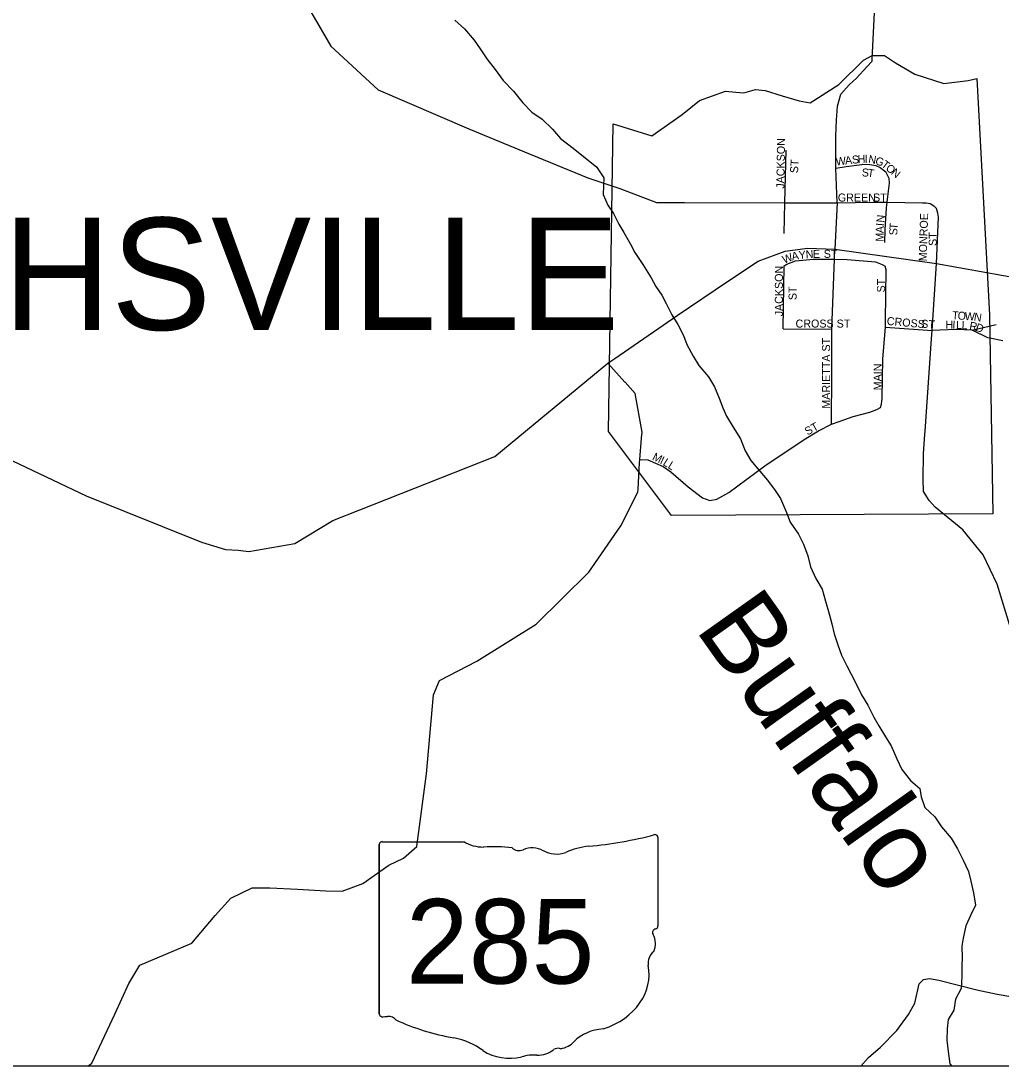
# Model space of a CAD drawing. Extents: x -22 to 431, y -18 to 160.
# Drawn here: x -3.877 to -2.717, y 14.134 to 15.371 of the extents above; entities that cross this region are included whole.
import ezdxf

# ---------------------------------------------------------------- set-up
doc = ezdxf.new("R2010")
doc.units = 0
for name, color, linetype in [('GM_X_Airport_Location_Class_2', 7, 'Continuous'), ('GM_X_Corporation_Text', 7, 'Continuous'), ('GM_X_County_ROW', 7, 'Continuous'), ('GM_X_County_Subdivision_Text', 7, 'Continuous'), ('GM_X_Interstate_Location', 7, 'Continuous'), ('GM_X_Major_River', 7, 'Continuous'), ('GM_X_Minor_River', 7, 'Continuous'), ('GM_X_Minor_River_Text', 7, 'Continuous'), ('GM_X_Rail_Line', 7, 'Continuous'), ('GM_X_Section', 7, 'Continuous'), ('GM_X_Section_Text', 7, 'Continuous')]:
    doc.layers.add(name, color=color, linetype=linetype)

msp = doc.modelspace()

# ---------------------------------------------------------------- linework, layer by layer
at = {"layer": 'GM_X_Airport_Location_Class_2'}
for p, q in [((-3.1234, 14.4049), (-3.1234, 14.3002)), ((-3.453, 14.3965), (-3.453, 14.1964)), ((-3.453, 14.1964), (-3.453, 14.3965)), ((-3.453, 14.1964), (-3.453, 14.3965)), ((-3.4497, 14.3999), (-3.3532, 14.3999)), ((-3.1234, 14.3002), (-3.1234, 14.3002))]:
    msp.add_line(p, q, dxfattribs=at)
for centre, major_axis, start_param, end_param in [((-3.2408, 14.6728), (0.3495, 0), 4.814394, 5.042369), ((-3.1271, 14.4053), (0.00367, 0), 6.141152, 7.989035), ((-3.4492, 14.3969), (0.00382, 0), 1.712693, 3.28349), ((-3.3302, 14.4232), (0.037, 0), 4.042523, 4.731795), ((-3.318, 14.2876), (0.133, 0), 1.404758, 1.657858), ((-3.2878, 14.398), (0.0107, 0), 3.836095, 5.185415), ((-3.2721, 14.3748), (0.0222, 0), 0.950623, 2.079405), ((-3.1962, 14.3388), (0.0703, 0), 1.699011, 2.107814), ((-3.2434, 14.4066), (0.0267, 0), 4.081561, 5.145723), ((-3.1243, 14.2925), (0.00568, 0), 1.883978, 3.671073), ((-3.1273, 14.2998), (0.00393, 0), 5.05454, 6.418171), ((-3.1604, 14.2793), (0.0341, 0), 5.934695, 6.695948), ((-3.1103, 14.2564), (0.0248, 0), 2.387724, 3.262537), ((-3.2212, 14.2431), (0.0874, 0), 5.101752, 6.440018), ((-3.4492, 14.1959), (0.00385, 0), 3.00124, 4.508301), ((-3.4486, 14.2164), (0.0294, 0), 4.665946, 4.897461), ((-3.4426, 14.1848), (0.0106, 0), 0.519207, 1.627899), ((-3.3088, 14.3646), (0.2524, 0), 4.195997, 4.488961), ((-3.1844, 14.1402), (0.0479, 0), 1.647645, 2.488434), ((-3.384, 14.1065), (0.079, 0), 0.823519, 1.323587), ((-3.2418, 14.1495), (0.00752, 0), 1.147584, 2.315152), ((-3.245, 14.177), (0.0282, 0), 4.937069, 5.64225), ((-3.2986, 14.1838), (0.0501, 0), 4.026481, 4.996735), ((-3.2696, 14.1146), (0.0412, 0), 1.495662, 1.94098), ((-3.266, 14.1688), (0.0267, 0), 4.691044, 5.507374)]:
    msp.add_ellipse(centre, major_axis=major_axis, ratio=0.8, start_param=start_param, end_param=end_param, dxfattribs=at)
at = {"layer": 'GM_X_County_ROW'}
for points in [[(-2.7998, 14.9946), (-2.7992, 15.0045), (-2.7938, 15.0839)], [(-2.8072, 14.8855), (-2.7998, 14.9946)], [(-3.1623, 14.9433), (-3.1625, 14.9435), (-3.1827, 14.9659), (-3.1745, 14.9716)], [(-3.1469, 14.817), (-3.1452, 14.8479), (-3.1449, 14.852), (-3.1427, 14.8772), (-3.1427, 14.8777)]]:
    msp.add_lwpolyline(points, dxfattribs=at)
at = {"layer": 'GM_X_County_Subdivision_Text'}
msp.add_lwpolyline([(-3.1764, 15.249), (-3.1305, 15.235), (-3.0948, 15.2601), (-3.0741, 15.2766), (-3.0435, 15.2875), (-3.0314, 15.2865), (-3.0219, 15.2855), (-3.008, 15.2898), (-2.9966, 15.2884), (-2.9765, 15.2821), (-2.9563, 15.2763), (-2.9434, 15.2738), (-2.9096, 15.2957), (-2.8803, 15.3245), (-2.8698, 15.3299), (-2.8554, 15.3297), (-2.8424, 15.3211), (-2.8196, 15.3077), (-2.7854, 15.2966), (-2.7565, 15.3001), (-2.7461, 15.3027), (-2.731, 15.023), (-2.7273, 14.7876), (-3.1074, 14.7857), (-3.1819, 14.8852)], close=True, dxfattribs=at)
at = {"layer": 'GM_X_Minor_River'}
for points in [[(-3.3635, 15.3718), (-3.3524, 15.3613), (-3.3406, 15.3481), (-3.3336, 15.3376), (-3.3259, 15.3259), (-3.316, 15.3131), (-3.3064, 15.3003), (-3.2941, 15.2875), (-3.2834, 15.2739), (-3.2726, 15.2627), (-3.2604, 15.2544), (-3.2482, 15.2428), (-3.2386, 15.2315), (-3.2237, 15.2203), (-3.2115, 15.2105), (-3.1962, 15.1982), (-3.1874, 15.185), (-3.1877, 15.1755), (-3.188, 15.1656), (-3.1825, 15.1528), (-3.176, 15.143), (-3.1698, 15.1305), (-3.1636, 15.1203)], [(-3.1636, 15.1203), (-3.1559, 15.1067), (-3.1509, 15.0969), (-3.1413, 15.0826), (-3.1316, 15.0668), (-3.1259, 15.0566), (-3.1189, 15.0464), (-3.1135, 15.0366), (-3.1069, 15.023), (-3.1, 15.0117), (-3.0931, 14.9985), (-3.0892, 14.9879), (-3.0818, 14.9743), (-3.0749, 14.963), (-3.0634, 14.9498), (-3.0565, 14.9378), (-3.051, 14.9245), (-3.0467, 14.9132), (-3.0421, 14.9034), (-3.0344, 14.8902), (-3.0259, 14.8766), (-3.0201, 14.8622), (-3.0135, 14.8509), (-3.0051, 14.8411), (-2.9936, 14.8276), (-2.9848, 14.8155), (-2.9786, 14.8057), (-2.9712, 14.7891), (-2.9669, 14.7778), (-2.957, 14.7635), (-2.9512, 14.7518), (-2.9461, 14.7381), (-2.9429, 14.7249), (-2.9367, 14.7113), (-2.929, 14.6985), (-2.9251, 14.6845), (-2.9208, 14.6694), (-2.9176, 14.6576), (-2.9148, 14.6459), (-2.9105, 14.6327), (-2.9062, 14.6206), (-2.9001, 14.6081), (-2.895, 14.5979), (-2.8881, 14.5851), (-2.8827, 14.5738), (-2.8753, 14.5613), (-2.868, 14.547), (-2.8622, 14.5368), (-2.8541, 14.524), (-2.8476, 14.5134), (-2.841, 14.4979), (-2.8348, 14.4851), (-2.8248, 14.4723), (-2.8137, 14.4629), (-2.8121, 14.4531), (-2.8078, 14.4402), (-2.796, 14.4293), (-2.7879, 14.4173), (-2.7764, 14.4041), (-2.7691, 14.3913), (-2.7625, 14.3781), (-2.7559, 14.3645), (-2.7532, 14.3531), (-2.75, 14.3395), (-2.7479, 14.3247), (-2.7531, 14.3133), (-2.759, 14.3003), (-2.7623, 14.2859), (-2.7641, 14.2764), (-2.7636, 14.2627), (-2.7639, 14.2533), (-2.7641, 14.2404), (-2.7647, 14.2263), (-2.7714, 14.2137), (-2.7732, 14.2008), (-2.7802, 14.1897), (-2.7813, 14.1784), (-2.7815, 14.1651), (-2.7799, 14.1518), (-2.7782, 14.137), (-2.7759, 14.1345)]]:
    msp.add_lwpolyline(points, dxfattribs=at)
at = {"layer": 'GM_X_Minor_River_Text'}
for points in [[(-2.7156, 14.9923), (-2.7309, 14.9953)], [(-2.8833, 14.1345), (-2.8743, 14.1448), (-2.86, 14.157), (-2.8409, 14.1765), (-2.827, 14.1953), (-2.8197, 14.209), (-2.8142, 14.2316), (-2.8094, 14.237), (-2.8022, 14.2382), (-2.7911, 14.2361), (-2.7461, 14.2245), (-2.7222, 14.2196), (-2.6896, 14.2141)]]:
    msp.add_lwpolyline(points, dxfattribs=at)
at = {"layer": 'GM_X_Rail_Line'}
for points in [[(-3.8813, 15.8449), (-3.787, 15.8126), (-3.74, 15.7954), (-3.6994, 15.7752), (-3.6638, 15.756), (-3.6357, 15.7287), (-3.6135, 15.6948), (-3.5898, 15.6545), (-3.5751, 15.6141), (-3.5702, 15.5944), (-3.5686, 15.5397), (-3.5675, 15.5146), (-3.5663, 15.4846), (-3.5623, 15.4489), (-3.5531, 15.4149), (-3.5328, 15.3795), (-3.5105, 15.341), (-3.4543, 15.2891), (-3.3469, 15.2432), (-3.2812, 15.216), (-3.2811, 15.216)], [(-2.8698, 15.325), (-2.8698, 15.3253), (-2.8669, 15.3886)], [(-2.9115, 15.1556), (-2.9131, 15.1967), (-2.9131, 15.2344), (-2.9123, 15.2534), (-2.911, 15.2698), (-2.9071, 15.2843), (-2.8973, 15.2951), (-2.8884, 15.3032), (-2.8764, 15.3163), (-2.8699, 15.3233), (-2.8698, 15.325)], [(-3.2811, 15.216), (-3.2063, 15.185), (-3.1685, 15.1727), (-3.125, 15.1558), (-3.0919, 15.1558)], [(-3.0919, 15.1558), (-3.0919, 15.1558), (-2.9732, 15.1556), (-2.9115, 15.1556)], [(-2.9115, 15.1556), (-2.9142, 15.1009), (-2.7938, 15.0839)], [(-3.1745, 14.9716), (-3.1745, 14.9716), (-3.1005, 15.0225), (-3.0411, 15.0625), (-3.0047, 15.0866), (-2.9729, 15.0985), (-2.9464, 15.1018), (-2.9142, 15.1009)], [(-2.7938, 15.0839), (-2.6884, 15.065), (-2.5604, 15.0459), (-2.5156, 15.0376), (-2.455, 15.0278)], [(-4.0467, 14.9261), (-3.7999, 14.8091), (-3.6635, 14.7541), (-3.6349, 14.7456), (-3.6201, 14.7446), (-3.6072, 14.7431), (-3.5531, 14.7526), (-3.5081, 14.78), (-3.3165, 14.8554), (-3.1827, 14.9659)], [(-3.1427, 14.8777), (-3.1421, 14.8842), (-3.1504, 14.9301), (-3.1623, 14.9433)], [(-2.6759, 14.1345), (-2.6831, 14.1498), (-2.6889, 14.1732), (-2.6896, 14.2141), (-2.6925, 14.3342), (-2.6886, 14.4447), (-2.689, 14.5022), (-2.6931, 14.5551), (-2.6978, 14.6073), (-2.706, 14.6516), (-2.7222, 14.7044), (-2.7385, 14.7393), (-2.7627, 14.7688), (-2.7844, 14.7864), (-2.7956, 14.7954), (-2.8024, 14.8035), (-2.8092, 14.8141), (-2.8097, 14.8286), (-2.8091, 14.8586), (-2.8075, 14.8819), (-2.8072, 14.8855)], [(-3.7976, 14.1345), (-3.793, 14.1378), (-3.7658, 14.196), (-3.7492, 14.232), (-3.7363, 14.2538), (-3.6748, 14.2798), (-3.6472, 14.3126), (-3.6285, 14.333), (-3.6032, 14.3455), (-3.5824, 14.3455), (-3.5497, 14.3437), (-3.5162, 14.3416), (-3.4969, 14.3415), (-3.4723, 14.3506), (-3.4419, 14.3723), (-3.4242, 14.3806), (-3.4084, 14.3941), (-3.3972, 14.4802), (-3.3887, 14.5738), (-3.3818, 14.5906), (-3.3377, 14.6133), (-3.2674, 14.6573), (-3.2053, 14.7187), (-3.1674, 14.7736), (-3.1471, 14.8135), (-3.1469, 14.8165), (-3.1469, 14.817)]]:
    msp.add_lwpolyline(points, dxfattribs=at)
at = {"layer": 'GM_X_Section'}
msp.add_line((-1.9192, 14.1345), (-8.7192, 14.1345), dxfattribs=at)
at = {"layer": 'GM_X_Section_Text'}
for points in [[(-2.974, 15.1192), (-2.9732, 15.1556), (-2.9717, 15.218)], [(-2.9131, 15.1967), (-2.9006, 15.1987), (-2.8824, 15.201)], [(-2.8824, 15.201), (-2.8822, 15.201), (-2.8812, 15.2012), (-2.8728, 15.2009), (-2.8658, 15.1997), (-2.8607, 15.1975), (-2.8538, 15.1922)], [(-2.8551, 15.1086), (-2.8545, 15.1242), (-2.8531, 15.1497), (-2.8522, 15.1562), (-2.8513, 15.163), (-2.8495, 15.179), (-2.8499, 15.1843), (-2.8538, 15.1922)], [(-2.9115, 15.1556), (-2.8687, 15.1564), (-2.8522, 15.1562), (-2.8103, 15.1557), (-2.806, 15.1554), (-2.8015, 15.1546), (-2.7971, 15.1521), (-2.7939, 15.1489)], [(-2.7938, 15.0839), (-2.7915, 15.1387), (-2.7922, 15.1435), (-2.7939, 15.1489)], [(-2.918, 14.8939), (-2.9178, 14.9543), (-2.9178, 15.006), (-2.9146, 15.0888), (-2.9142, 15.1009)], [(-2.9741, 15.0809), (-2.9711, 15.0832), (-2.9605, 15.087), (-2.9393, 15.0891), (-2.9146, 15.0888), (-2.8994, 15.0886), (-2.8659, 15.0858), (-2.858, 15.0828), (-2.8545, 15.0805)], [(-2.9751, 15.0064), (-2.9741, 15.0809)], [(-2.8542, 15.0165), (-2.8534, 15.0763), (-2.8545, 15.0805)], [(-2.8602, 14.9133), (-2.8589, 14.9176), (-2.858, 14.9247), (-2.8572, 14.9711), (-2.8543, 15.0085), (-2.8542, 15.0165)], [(-2.7518, 15.0048), (-2.7232, 15.0115)], [(-2.9751, 15.0064), (-2.9178, 15.006)], [(-2.8543, 15.0085), (-2.7992, 15.0045)], [(-2.7309, 14.9953), (-2.7333, 14.9958), (-2.7518, 15.0048), (-2.7715, 15.0056), (-2.7992, 15.0045)], [(-2.909, 14.897), (-2.8923, 14.9027), (-2.8727, 14.9079), (-2.8645, 14.911), (-2.8602, 14.9133)], [(-3.1449, 14.852), (-3.1355, 14.8514), (-3.1172, 14.8437), (-3.108, 14.8372), (-3.0877, 14.8198), (-3.0707, 14.8065), (-3.0621, 14.8033), (-3.0536, 14.8049), (-3.0395, 14.813), (-2.9969, 14.8444), (-2.9506, 14.8758), (-2.9334, 14.8857), (-2.918, 14.8939), (-2.909, 14.897)]]:
    msp.add_lwpolyline(points, dxfattribs=at)

# ---------------------------------------------------------------- texts
at = {"layer": 'GM_X_Airport_Location_Class_2'}
msp.add_text('285', height=0.1, dxfattribs=at).set_placement((-3.4216, 14.2321))
at = {"layer": 'GM_X_Corporation_Text'}
for s, rotation, p in [('JACKSON', 89.0876, (-2.9739, 15.1722)), ('ST', 86.4126, (-2.9578, 15.1904)), ('W', 6.1489, (-2.9125, 15.1996)), ('A', 6.1543, (-2.9017, 15.2008)), ('S', 6.1461, (-2.8934, 15.2017)), ('H', 3.7835, (-2.8869, 15.2024)), ('I', 359.5193, (-2.8788, 15.2029)), ('N', 350.7353, (-2.875, 15.2029)), ('G', 340.0785, (-2.8672, 15.2017)), ('S', 358.4422, (-2.8823, 15.1868)), ('T', 351.1126, (-2.876, 15.1866)), ('T', 322.7695, (-2.86, 15.1992)), ('O', 320.4323, (-2.8548, 15.1952)), ('N', 320.2, (-2.8484, 15.1899)), ('GREEN', 0, (-2.9106, 15.1571)), ('ST', 0, (-2.8689, 15.1571)), ('N', 84.4177, (-2.8557, 15.1319)), ('MONROE', 88.0919, (-2.8056, 15.0863)), ('A', 87.8797, (-2.8564, 15.1195)), ('I', 85.2291, (-2.8561, 15.1278)), ('S', 88.9618, (-2.8403, 15.1171)), ('T', 85.3498, (-2.8402, 15.1236)), ('ST', 90, (-2.7936, 15.1046)), ('M', 89.4718, (-2.8564, 15.1096)), ('W', 21.2644, (-2.9741, 15.0835)), ('A', 11.73, (-2.9644, 15.0873)), ('Y', 5.0777, (-2.9565, 15.089)), ('N', 3.9595, (-2.9483, 15.0897)), ('E', 1.202, (-2.9401, 15.0903)), ('ST', 0, (-2.9273, 15.0905)), ('JACKSON', 90, (-2.9756, 15.0213)), ('ST', 90, (-2.8548, 15.0496)), ('ST', 90, (-2.9594, 15.0405)), ('T', 356.5004, (-2.7757, 15.018)), ('O', 356.4796, (-2.7691, 15.0176)), ('W', 356.5027, (-2.7607, 15.017)), ('N', 350.6922, (-2.7502, 15.0164)), ('CROSS ST', 0, (-2.9606, 15.008)), ('CROSS', 354.8033, (-2.853, 15.0113)), ('ST', 356.4254, (-2.8122, 15.008)), ('H', 358.5794, (-2.7834, 15.0068)), ('I', 358.557, (-2.7751, 15.0066)), ('L', 358.569, (-2.7709, 15.0065)), ('L', 357.5128, (-2.7643, 15.0063)), ('R', 349.8711, (-2.7555, 15.0058)), ('D', 341.3577, (-2.7485, 15.0045)), ('MARIETTA ST', 90, (-2.9198, 14.9121)), ('MAIN', 90, (-2.8589, 14.9338)), ('ST', 29.7432, (-2.9464, 14.8802)), ('M', 334.16, (-3.1308, 14.852)), ('I', 334.1402, (-3.1218, 14.8476)), ('L', 328.0757, (-3.1183, 14.8459)), ('L', 328.3644, (-3.1125, 14.8424))]:
    msp.add_text(s, height=0.00947, rotation=rotation, dxfattribs=at).set_placement(p)
at = {"layer": 'GM_X_Interstate_Location'}
msp.add_text('SARAHSVILLE', height=0.132576, rotation=0, dxfattribs=at).set_placement((-4.3809, 15.0053))
at = {"layer": 'GM_X_Major_River'}
msp.add_text('Buffalo', height=0.09472, rotation=305.3434, dxfattribs=at).set_placement((-3.0807, 14.6521))

doc.saveas('drawing.dxf')
